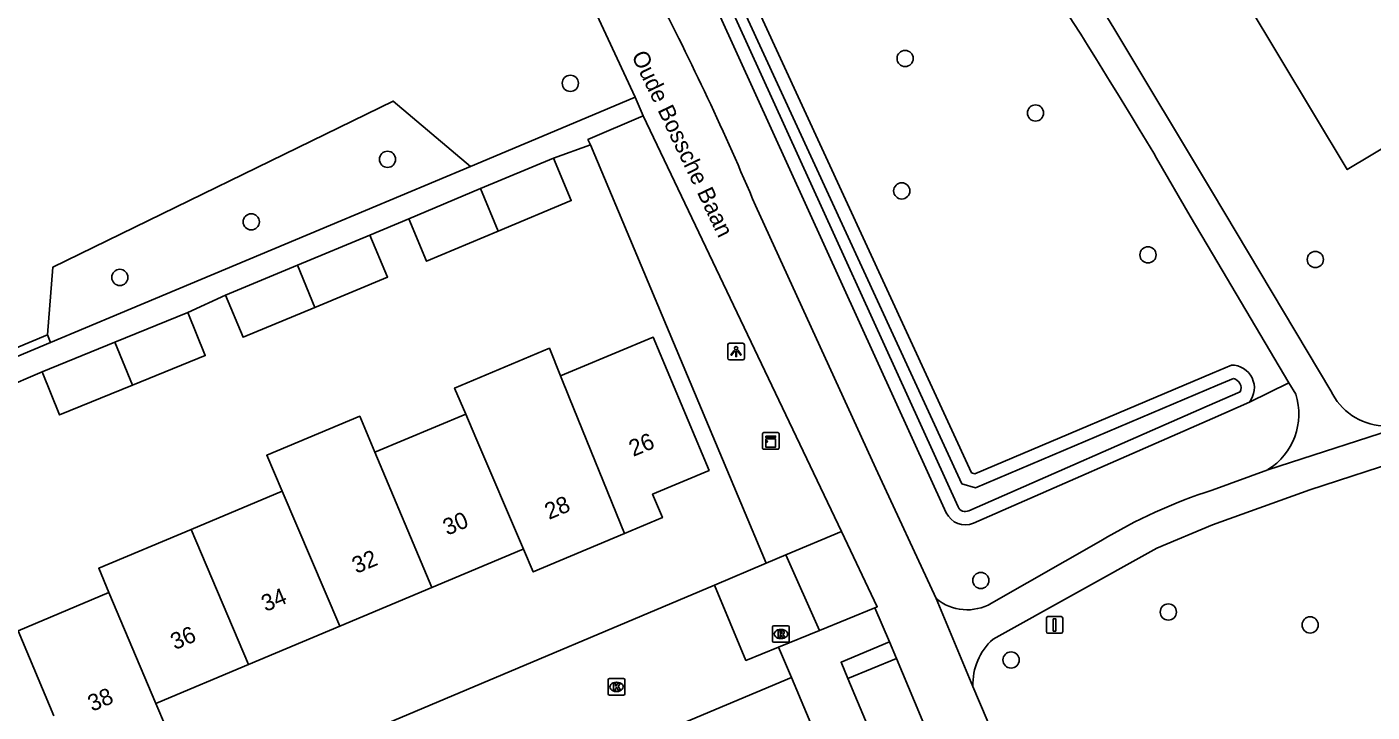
# Model space of a CAD drawing. Extents: x 157767 to 159171, y 387842 to 389425.
# Drawn here: x 158928.5 to 159009.6, y 388369.9 to 388411.3 of the extents above; entities that cross this region are included whole.
import ezdxf

# ---------------------------------------------------------------- set-up
doc = ezdxf.new("R2010")
doc.units = 0
for name, color, linetype in [('IMGEO_Berm_groen', 7, 'Continuous'), ('IMGEO_Boom', 7, 'Continuous'), ('IMGEO_Fietspad_gesloten', 7, 'Continuous'), ('IMGEO_Groenvoorziening', 7, 'Continuous'), ('IMGEO_Kast', 7, 'Continuous'), ('IMGEO_Kolk', 7, 'Continuous'), ('IMGEO_Lichtpunt', 7, 'Continuous'), ('IMGEO_Openbare_ruimte_label', 7, 'Continuous'), ('IMGEO_Pand', 7, 'Continuous'), ('IMGEO_Pand_nummerreeks', 7, 'Continuous'), ('IMGEO_Parkeervlak_open', 7, 'Continuous'), ('IMGEO_Rijbaan_lokaal_open', 7, 'Continuous'), ('IMGEO_Rioolput', 7, 'Continuous'), ('IMGEO_Verkeersbordpaal', 7, 'Continuous'), ('IMGEO_Voetpad_gesloten', 7, 'Continuous'), ('IMGEO_Voetpad_open', 7, 'Continuous'), ('IMGEO_Waterloop', 7, 'Continuous')]:
    doc.layers.add(name, color=color, linetype=linetype)

msp = doc.modelspace()

# ---------------------------------------------------------------- linework, layer by layer
at = {"layer": 'IMGEO_Berm_groen'}
for points in [[(158983.946, 388381.961), (158958.733, 388437.356), (158955.796, 388444.217)], [(159004.606, 388389.804), (159002.227, 388388.624)], [(159002.227, 388388.624), (159000, 388387.648), (158985.592, 388381.333)]]:
    msp.add_lwpolyline(points, dxfattribs=at)
msp.add_arc((158985.087, 388382.48), 1.253, 204.45972, 293.77347, dxfattribs=at)
at = {"layer": 'IMGEO_Boom'}
for centre in [(158981.466, 388409.366), (158961.279, 388407.869), (158989.329, 388406.075), (158950.252, 388403.281), (158981.261, 388401.376), (158942.034, 388399.51), (158996.112, 388397.518), (159006.202, 388397.236), (158934.11, 388396.156), (158986.031, 388377.871), (158997.34, 388375.967), (159005.89, 388375.189), (158987.855, 388373.076)]:
    msp.add_circle(centre, 0.489, dxfattribs=at)
at = {"layer": 'IMGEO_Fietspad_gesloten'}
for points in [[(158957.433, 388423.731), (158965.184, 388407.027)], [(158965.184, 388407.027), (158965.661, 388405.91)], [(158965.661, 388405.91), (158977.622, 388380.827)], [(158983.336, 388376.776), (158979.69, 388384.637), (158972.442, 388400.496)], [(158977.622, 388380.827), (158979.787, 388376.286), (158979.637, 388376.224)], [(158985.556, 388371.478), (158983.336, 388376.776)], [(158979.637, 388376.224), (158980.522, 388374.161)], [(158980.522, 388374.161), (158980.936, 388373.173)], [(159006.58, 388311.043), (159000, 388326.968), (158990.757, 388349.724), (158980.936, 388373.173)], [(159010.278, 388312.299), (159009.34, 388314.661), (159003.467, 388329.206), (159000, 388337.149), (158994.882, 388349.556), (158985.556, 388371.478)]]:
    msp.add_lwpolyline(points, dxfattribs=at)
msp.add_arc((158809.264, 388331.751), 177.068, 22.84498, 27.44087, dxfattribs=at)
at = {"layer": 'IMGEO_Groenvoorziening'}
for points in [[(159001.138, 388390.868), (159000, 388390.385), (158985.666, 388384.306), (158985.47, 388384.366), (158957.449, 388445.194)], [(159020.441, 388410.031), (159008.125, 388402.667), (159000, 388416.194), (158994.712, 388424.998), (159000, 388428.16), (159007.071, 388432.388), (159020.441, 388410.031)], [(158955.249, 388402.857), (158950.592, 388406.799), (158930.071, 388396.779), (158929.749, 388392.688)], [(158973.092, 388378.915), (158962.485, 388404.156)], [(158974.272, 388379.413), (158977.622, 388380.827)]]:
    msp.add_lwpolyline(points, dxfattribs=at)
msp.add_arc((159001.14, 388389.483), 1.385, 321.69401, 90.08005, dxfattribs=at)
at = {"layer": 'IMGEO_Kast'}
for p, q in [((158972.862, 388385.87), (158972.862, 388386.711)), ((158972.862, 388386.711), (158972.862, 388385.87)), ((158972.937, 388386.795), (158973.778, 388386.795)), ((158973.778, 388386.795), (158972.937, 388386.795)), ((158973.862, 388386.72), (158973.862, 388385.879)), ((158973.862, 388385.879), (158973.862, 388386.72)), ((158973.787, 388385.795), (158972.946, 388385.795)), ((158972.946, 388385.795), (158973.787, 388385.795))]:
    msp.add_line(p, q, dxfattribs=at)
for points in [[(158973.057, 388386.585), (158973.657, 388386.585), (158973.657, 388386.5), (158973.057, 388386.5), (158973.057, 388386.585)], [(158973.057, 388386.41), (158973.657, 388386.41), (158973.657, 388385.921), (158973.057, 388385.921), (158973.057, 388386.41)]]:
    msp.add_lwpolyline(points, dxfattribs=at)
msp.add_circle((158973.141, 388386.259), 0.0377, dxfattribs=at)
for centre, start, end in [((158972.94, 388386.717), 92.4484, 184.28452), ((158972.94, 388386.717), 92.4484, 184.28452), ((158973.784, 388386.717), 2.4484, 94.28452), ((158973.784, 388386.717), 2.4484, 94.28452), ((158972.94, 388385.873), 182.4484, 274.28452), ((158972.94, 388385.873), 182.4484, 274.28452), ((158973.784, 388385.873), 272.4484, 4.28452), ((158973.784, 388385.873), 272.4484, 4.28452)]:
    msp.add_arc(centre, 0.0779, start, end, dxfattribs=at)
at = {"layer": 'IMGEO_Kolk'}
for p, q in [((158963.563, 388371.025), (158963.563, 388371.877)), ((158963.638, 388371.951), (158964.49, 388371.951)), ((158964.564, 388371.877), (158964.564, 388371.025)), ((158964.074, 388371.171), (158964.049, 388371.171)), ((158964.051, 388371.731), (158964.076, 388371.731)), ((158964.49, 388370.951), (158963.638, 388370.951))]:
    msp.add_line(p, q, dxfattribs=at)
for points in [[(158963.563, 388371.025), (158963.563, 388371.877)], [(158963.638, 388371.951), (158964.49, 388371.951)], [(158964.564, 388371.877), (158964.564, 388371.025)], [(158963.884, 388371.651), (158964.007, 388371.651), (158964.007, 388371.5), (158964.137, 388371.651), (158964.301, 388371.651), (158964.155, 388371.5), (158964.308, 388371.251), (158964.156, 388371.251), (158964.071, 388371.415), (158964.007, 388371.348), (158964.007, 388371.251), (158963.884, 388371.251), (158963.884, 388371.651)], [(158964.49, 388370.951), (158963.638, 388370.951)]]:
    msp.add_lwpolyline(points, dxfattribs=at)
for centre, start, end in [((158963.64, 388371.875), 91.55205, 178.44795), ((158963.64, 388371.875), 91.55205, 178.44795), ((158964.488, 388371.875), 1.55205, 88.44795), ((158964.488, 388371.875), 1.55205, 88.44795), ((158963.64, 388371.027), 181.55205, 268.44795), ((158963.64, 388371.027), 181.55205, 268.44795), ((158964.488, 388371.027), 271.55205, 358.44795), ((158964.488, 388371.027), 271.55205, 358.44795)]:
    msp.add_arc(centre, 0.0765, start, end, dxfattribs=at)
for centre, major_axis, ratio, start_param, end_param in [((158964.05, 388371.451), (-0.387, 0.002), 0.722429, 4.712389, 7.853982), ((158964.075, 388371.451), (-0.39, 0.002), 0.717154, 1.570796, 4.712389)]:
    msp.add_ellipse(centre, major_axis=major_axis, ratio=ratio, start_param=start_param, end_param=end_param, dxfattribs=at)
at = {"layer": 'IMGEO_Lichtpunt'}
for p, q in [((158970.777, 388392.087), (158970.777, 388391.28)), ((158970.777, 388392.087), (158970.777, 388391.28)), ((158971.679, 388392.182), (158970.871, 388392.182)), ((158971.679, 388392.182), (158970.871, 388392.182)), ((158971.773, 388391.28), (158971.773, 388392.087)), ((158971.773, 388391.28), (158971.773, 388392.087)), ((158970.871, 388391.186), (158971.679, 388391.186)), ((158970.871, 388391.186), (158971.679, 388391.186))]:
    msp.add_line(p, q, dxfattribs=at)
for points in [[(158971.151, 388391.751), (158971.19, 388391.723), (158971.002, 388391.461), (158970.964, 388391.488), (158971.151, 388391.751)], [(158971.253, 388391.703), (158971.3, 388391.703), (158971.3, 388391.381), (158971.253, 388391.381), (158971.253, 388391.703)], [(158971.363, 388391.723), (158971.401, 388391.75), (158971.588, 388391.488), (158971.549, 388391.46), (158971.363, 388391.723)]]:
    msp.add_lwpolyline(points, dxfattribs=at)
msp.add_circle((158971.276, 388391.885), 0.0994, dxfattribs=at)
for centre, start, end in [((158970.871, 388392.087), 90, 180), ((158970.871, 388392.087), 90, 180), ((158971.679, 388392.087), 0, 90), ((158971.679, 388392.087), 0, 90), ((158970.871, 388391.28), 180, 270), ((158970.871, 388391.28), 180, 270), ((158971.679, 388391.28), 270, 0), ((158971.679, 388391.28), 270, 360)]:
    msp.add_arc(centre, 0.0946, start, end, dxfattribs=at)
at = {"layer": 'IMGEO_Pand'}
for points in [[(158960.256, 388403.354), (158955.862, 388401.513)], [(158960.256, 388403.354), (158961.33, 388400.79), (158956.928, 388398.946)], [(158955.862, 388401.513), (158951.532, 388399.7)], [(158956.928, 388398.946), (158955.862, 388401.513)], [(158956.928, 388398.946), (158952.605, 388397.136), (158951.532, 388399.7)], [(158949.195, 388398.712), (158944.829, 388396.891)], [(158949.195, 388398.712), (158950.253, 388396.175), (158945.878, 388394.351)], [(158944.829, 388396.891), (158940.482, 388395.078)], [(158945.878, 388394.351), (158944.829, 388396.891)], [(158945.878, 388394.351), (158941.54, 388392.542), (158940.482, 388395.078)], [(158938.201, 388394.046), (158933.811, 388392.256)], [(158938.201, 388394.046), (158939.263, 388391.443), (158934.869, 388389.651)], [(158933.811, 388392.256), (158929.417, 388390.464)], [(158934.869, 388389.651), (158933.811, 388392.256)], [(158960.69, 388390.209), (158961.658, 388390.616), (158966.267, 388392.553), (158969.646, 388384.511), (158966.232, 388383.077), (158966.827, 388381.662), (158964.547, 388380.704)], [(158960.69, 388390.209), (158960.01, 388391.885), (158954.296, 388389.481), (158954.97, 388387.907)], [(158934.869, 388389.651), (158930.479, 388387.861), (158929.417, 388390.464)], [(158964.547, 388380.704), (158961.235, 388388.865), (158960.69, 388390.209)], [(158943.898, 388383.254), (158942.968, 388385.427), (158948.575, 388387.782), (158949.49, 388385.604)], [(158949.49, 388385.604), (158954.97, 388387.907)], [(158954.97, 388387.907), (158955.578, 388386.487), (158958.454, 388379.766)], [(158949.49, 388385.604), (158952.919, 388377.441)], [(158938.408, 388380.947), (158943.898, 388383.254)], [(158943.898, 388383.254), (158947.38, 388375.113)], [(158933.455, 388377.138), (158932.838, 388378.607), (158938.408, 388380.947)], [(158941.864, 388372.796), (158938.408, 388380.947)], [(158958.454, 388379.766), (158959.043, 388378.391), (158964.547, 388380.704)], [(158958.454, 388379.766), (158958.325, 388379.712), (158952.919, 388377.441)], [(158930.121, 388369.712), (158927.969, 388374.833), (158933.455, 388377.138)], [(158936.287, 388370.452), (158933.455, 388377.138)], [(158952.919, 388377.441), (158947.38, 388375.113)], [(158947.38, 388375.113), (158941.864, 388372.796)], [(158941.864, 388372.796), (158936.427, 388370.511), (158936.287, 388370.452)], [(158936.287, 388370.452), (158936.871, 388369.072), (158933.643, 388367.715), (158934.233, 388366.312), (158932.038, 388365.39), (158931.923, 388365.342)]]:
    msp.add_lwpolyline(points, dxfattribs=at)
at = {"layer": 'IMGEO_Parkeervlak_open'}
for points in [[(158974.272, 388379.413), (158973.092, 388378.915)], [(158976.31, 388374.855), (158974.272, 388379.413)], [(158969.976, 388377.598), (158973.092, 388378.915)]]:
    msp.add_lwpolyline(points, dxfattribs=at)
at = {"layer": 'IMGEO_Rijbaan_lokaal_open'}
for points in [[(158929.749, 388392.688), (158923.193, 388389.964), (158908.936, 388384.041), (158905.959, 388385.24), (158905.674, 388384.767)], [(158929.938, 388392.233), (158908.94, 388383.419)], [(158929.938, 388392.233), (158929.749, 388392.688)]]:
    msp.add_lwpolyline(points, dxfattribs=at)
at = {"layer": 'IMGEO_Rioolput'}
for p, q in [((158973.474, 388374.215), (158973.474, 388375.067)), ((158973.549, 388375.141), (158974.401, 388375.141)), ((158974.475, 388375.067), (158974.475, 388374.215)), ((158973.985, 388374.361), (158973.96, 388374.361)), ((158973.962, 388374.921), (158973.987, 388374.921)), ((158974.401, 388374.141), (158973.549, 388374.141))]:
    msp.add_line(p, q, dxfattribs=at)
for points in [[(158973.474, 388374.215), (158973.474, 388375.067)], [(158973.549, 388375.141), (158974.401, 388375.141)], [(158974.475, 388375.067), (158974.475, 388374.215)], [(158974.063, 388374.839), (158973.811, 388374.841), (158973.811, 388374.441)], [(158973.811, 388374.441), (158973.935, 388374.441), (158973.935, 388374.603), (158973.946, 388374.603)], [(158973.989, 388374.76), (158973.935, 388374.76), (158973.935, 388374.679)], [(158973.935, 388374.679), (158973.987, 388374.679)], [(158973.993, 388374.574), (158974.064, 388374.441), (158974.204, 388374.441), (158974.139, 388374.567)], [(158974.401, 388374.141), (158973.549, 388374.141)]]:
    msp.add_lwpolyline(points, dxfattribs=at)
for centre, radius, start, end in [((158973.551, 388375.065), 0.0765, 91.55205, 178.44795), ((158973.551, 388375.065), 0.0765, 91.55205, 178.44795), ((158974.399, 388375.065), 0.0765, 1.55205, 88.44795), ((158974.399, 388375.065), 0.0765, 1.55205, 88.44795), ((158973.945, 388374.55), 0.0533, 26.02933, 88.69889), ((158973.971, 388374.868), 0.19, 274.7715, 282.96867), ((158973.995, 388374.664), 0.0964, 77.00612, 93.18647), ((158974.009, 388374.721), 0.0378, 276.66336, 79.67722), ((158974.062, 388374.729), 0.109, 350.36119, 89.41601), ((158974.06, 388374.729), 0.112, 277.58423, 350.98172), ((158974.044, 388374.514), 0.108, 29.51342, 73.79051), ((158973.551, 388374.217), 0.0765, 181.55205, 268.44795), ((158973.551, 388374.217), 0.0765, 181.55205, 268.44795), ((158974.399, 388374.217), 0.0765, 271.55205, 358.44795), ((158974.399, 388374.217), 0.0765, 271.55205, 358.44795)]:
    msp.add_arc(centre, radius, start, end, dxfattribs=at)
for centre, major_axis, ratio, start_param, end_param in [((158973.961, 388374.641), (-0.387, 0.002), 0.722429, 4.712389, 7.853982), ((158973.986, 388374.641), (-0.39, 0.002), 0.717154, 1.570796, 4.712389)]:
    msp.add_ellipse(centre, major_axis=major_axis, ratio=ratio, start_param=start_param, end_param=end_param, dxfattribs=at)
at = {"layer": 'IMGEO_Verkeersbordpaal'}
for p, q in [((158989.981, 388374.79), (158989.981, 388375.59)), ((158989.981, 388375.59), (158989.981, 388374.79)), ((158990.081, 388375.69), (158990.871, 388375.69)), ((158990.871, 388375.69), (158990.081, 388375.69)), ((158990.971, 388375.59), (158990.971, 388374.79)), ((158990.971, 388374.79), (158990.971, 388375.59)), ((158990.871, 388374.69), (158990.081, 388374.69)), ((158990.081, 388374.69), (158990.871, 388374.69))]:
    msp.add_line(p, q, dxfattribs=at)
msp.add_lwpolyline([(158990.401, 388375.565), (158990.551, 388375.565), (158990.551, 388374.815), (158990.401, 388374.815), (158990.401, 388375.565)], dxfattribs=at)
for centre, start, end in [((158990.081, 388375.59), 90, 180), ((158990.081, 388375.59), 90, 180), ((158990.871, 388375.59), 0, 90), ((158990.871, 388375.59), 360, 90), ((158990.081, 388374.79), 180, 270), ((158990.081, 388374.79), 180, 270), ((158990.871, 388374.79), 270, 0), ((158990.871, 388374.79), 270, 0)]:
    msp.add_arc(centre, 0.1, start, end, dxfattribs=at)
at = {"layer": 'IMGEO_Voetpad_gesloten'}
for points in [[(159007.139, 388389.322), (159000, 388401.288), (158994.045, 388411.192)], [(158996.457, 388403.651), (158996.634, 388403.344), (158998.652, 388399.842), (159000, 388397.569), (159004.606, 388389.804)], [(159005.019, 388389.108), (159004.606, 388389.804)], [(159012.163, 388387.395), (159003.341, 388384.557)], [(158986.766, 388374.325), (158996.647, 388379.814), (159000, 388381.221), (159005.865, 388383.347), (159011.801, 388385.265)], [(159003.341, 388384.557), (158999.99, 388383.329)], [(158993.264, 388380.261), (158986.672, 388376.497)]]:
    msp.add_lwpolyline(points, dxfattribs=at)
for centre, radius, start, end in [((158596.919, 388163.285), 466.269, 31.03155, 37.64989), ((158707.706, 388238.527), 334.37, 31.09028, 37.39298), ((159001.261, 388387.909), 3.945, 301.82642, 17.69469), ((159010.449, 388390.847), 3.644, 204.73037, 266.82411), ((159009.809, 388352.896), 31.978, 107.88193, 121.15736), ((158985.204, 388379.029), 2.927, 230.33583, 300.10278), ((158989.196, 388371.612), 3.642, 131.8457, 182.10246)]:
    msp.add_arc(centre, radius, start, end, dxfattribs=at)
at = {"layer": 'IMGEO_Voetpad_open'}
for points in [[(158965.184, 388407.027), (158961.841, 388405.624), (158955.249, 388402.857)], [(158962.485, 388404.156), (158962.341, 388404.468), (158965.661, 388405.91)], [(158962.485, 388404.156), (158960.256, 388403.354)], [(158955.249, 388402.857), (158929.938, 388392.233)], [(158951.532, 388399.7), (158949.195, 388398.712)], [(158940.482, 388395.078), (158938.201, 388394.046)], [(158929.417, 388390.464), (158926.987, 388389.412)], [(158937.782, 388357.912), (158935.672, 388363.11), (158969.976, 388377.598)], [(158969.976, 388377.598), (158971.863, 388373.052), (158973.825, 388373.847)], [(158979.637, 388376.224), (158976.31, 388374.855)], [(158973.825, 388373.847), (158976.31, 388374.855)], [(158973.825, 388373.847), (158974.612, 388372.008)], [(158980.522, 388374.161), (158977.604, 388372.936), (158978.019, 388371.948)], [(158980.936, 388373.173), (158978.019, 388371.948)], [(158974.612, 388372.008), (158952.865, 388362.877)], [(159005.739, 388297.968), (159000, 388311.619), (158974.612, 388372.008)], [(158978.019, 388371.948), (159000, 388319.621), (159008.145, 388300.117)]]:
    msp.add_lwpolyline(points, dxfattribs=at)
at = {"layer": 'IMGEO_Waterloop'}
for points in [[(158984.659, 388382.324), (158959.464, 388437.679), (158956.585, 388444.405)], [(158956.865, 388444.551), (158984.894, 388383.706), (158985.71, 388383.456), (159000.312, 388389.649), (159001.26, 388390.051)], [(159001.674, 388389.255), (158999.679, 388388.38), (158985.302, 388382.079)]]:
    msp.add_lwpolyline(points, dxfattribs=at)
for centre, radius, start, end in [((159001.144, 388389.485), 0.578, 336.57214, 78.38578), ((158985.092, 388382.495), 0.466, 201.56525, 296.71842)]:
    msp.add_arc(centre, radius, start, end, dxfattribs=at)

# ---------------------------------------------------------------- texts
at = {"layer": 'IMGEO_Openbare_ruimte_label'}
msp.add_text('Oude Bossche Baan', height=1, rotation=295.59142, dxfattribs=at).set_placement((158964.942, 388409.544))
at = {"layer": 'IMGEO_Pand_nummerreeks'}
for s, rotation, p in [('26', 22.78653, (158965.07, 388385.323)), ('28', 22.79226, (158959.99, 388381.523)), ('30', 22.79226, (158953.852, 388380.566)), ('32', 22.79226, (158948.372, 388378.263)), ('34', 22.79095, (158942.9, 388375.965)), ('36', 22.79226, (158937.426, 388373.665)), ('38', 22.79226, (158932.439, 388369.943))]:
    msp.add_text(s, height=1, rotation=rotation, dxfattribs=at).set_placement(p)

doc.saveas('drawing.dxf')
